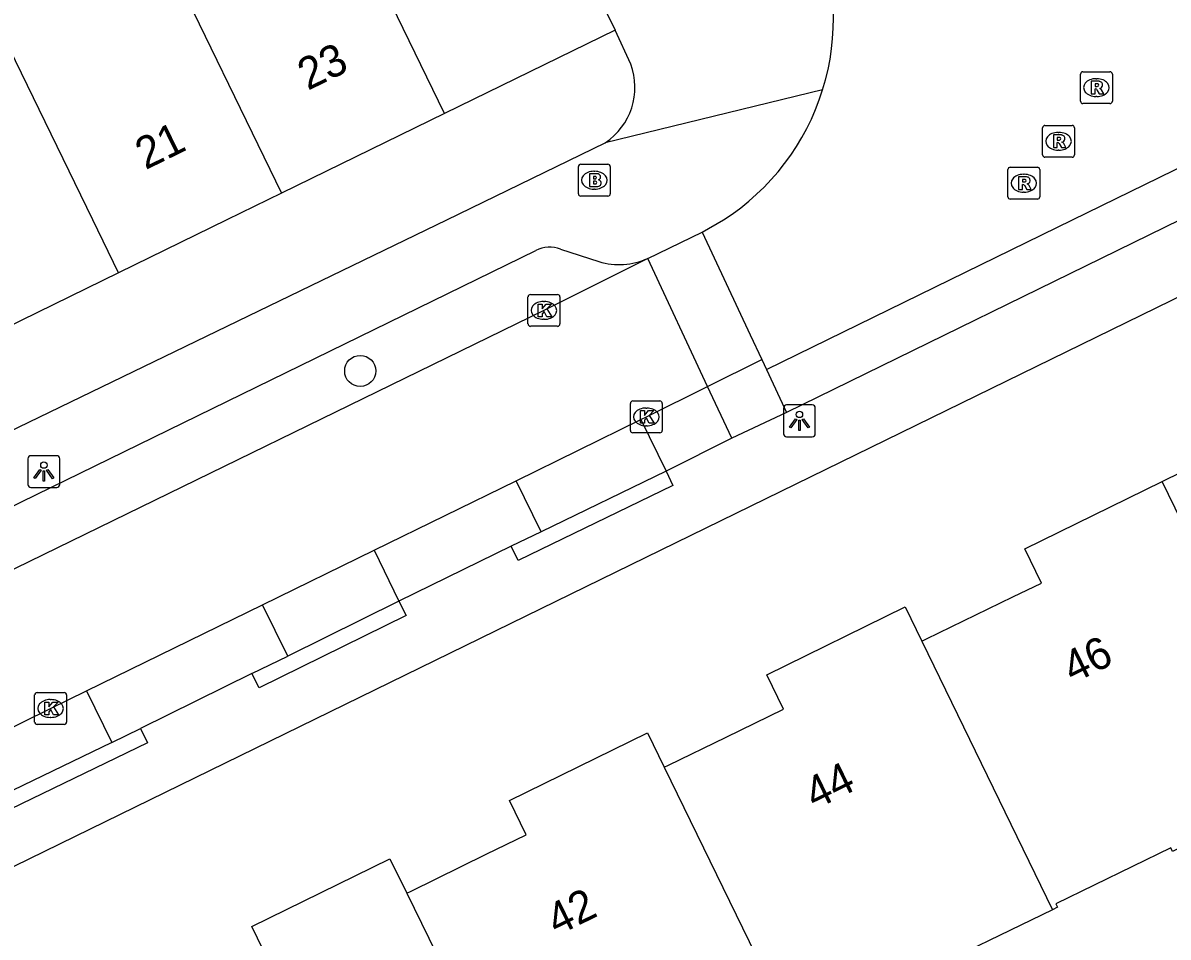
# Model space of a CAD drawing. Extents: x 160457 to 162082, y 388340 to 389736.
# Drawn here: x 160836.83 to 160872.78, y 388727.48 to 388756.19 of the extents above; entities that cross this region are included whole.
import ezdxf

# ---------------------------------------------------------------- set-up
doc = ezdxf.new("R2010")
doc.units = 0
for name, color, linetype in [('IMGEO_Boom', 7, 'Continuous'), ('IMGEO_Brandkraan', 7, 'Continuous'), ('IMGEO_Kolk', 7, 'Continuous'), ('IMGEO_Lichtpunt', 7, 'Continuous'), ('IMGEO_Pand', 7, 'Continuous'), ('IMGEO_Pand_nummerreeks', 7, 'Continuous'), ('IMGEO_Parkeervlak_open', 7, 'Continuous'), ('IMGEO_Rijbaan_lokaal_gesloten', 7, 'Continuous'), ('IMGEO_Rijbaan_lokaal_open', 7, 'Continuous'), ('IMGEO_Rioolput', 7, 'Continuous'), ('IMGEO_Voetpad_open', 7, 'Continuous')]:
    doc.layers.add(name, color=color, linetype=linetype)

msp = doc.modelspace()

# ---------------------------------------------------------------- linework, layer by layer
at = {"layer": 'IMGEO_Boom'}
msp.add_circle((160847.424, 388745.255), 0.489, dxfattribs=at)
at = {"layer": 'IMGEO_Brandkraan'}
for p, q in [((160854.347, 388751.746), (160855.199, 388751.746)), ((160854.272, 388750.82), (160854.272, 388751.672)), ((160854.76, 388751.526), (160854.785, 388751.526)), ((160855.273, 388751.672), (160855.273, 388750.82)), ((160855.199, 388750.746), (160854.347, 388750.746)), ((160854.783, 388750.966), (160854.758, 388750.966))]:
    msp.add_line(p, q, dxfattribs=at)
for points in [[(160854.347, 388751.746), (160855.199, 388751.746)], [(160854.272, 388750.82), (160854.272, 388751.672)], [(160854.62, 388751.446), (160854.62, 388751.046), (160854.833, 388751.046)], [(160854.851, 388751.446), (160854.62, 388751.446)], [(160854.799, 388751.365), (160854.745, 388751.365), (160854.745, 388751.289)], [(160855.273, 388751.672), (160855.273, 388750.82)], [(160854.745, 388751.289), (160854.798, 388751.289)], [(160854.807, 388751.213), (160854.745, 388751.213), (160854.745, 388751.132)], [(160854.745, 388751.132), (160854.807, 388751.132)], [(160855.199, 388750.746), (160854.347, 388750.746)]]:
    msp.add_lwpolyline(points, dxfattribs=at)
for centre, radius, start, end in [((160854.349, 388751.67), 0.0765, 91.552, 178.448), ((160854.349, 388751.67), 0.0765, 91.552, 178.448), ((160855.197, 388751.67), 0.0765, 1.552, 88.448), ((160855.197, 388751.67), 0.0765, 1.552, 88.448), ((160854.8, 388751.327), 0.0379, 267.8285, 90.9355), ((160854.855, 388751.301), 0.145, 59.4692, 91.5367), ((160854.88, 388751.348), 0.0922, 285.5137, 58.1501), ((160854.808, 388751.172), 0.0404, 269.8759, 90.5077), ((160854.839, 388751.297), 0.251, 268.6676, 293.5347), ((160854.885, 388751.156), 0.105, 301.3115, 78.989), ((160854.349, 388750.822), 0.0765, 181.552, 268.448), ((160854.349, 388750.822), 0.0765, 181.552, 268.448), ((160855.197, 388750.822), 0.0765, 271.552, 358.448), ((160855.197, 388750.822), 0.0765, 271.552, 358.448)]:
    msp.add_arc(centre, radius, start, end, dxfattribs=at)
for centre, major_axis, ratio, start_param, end_param in [((160854.759, 388751.246), (-0.387, 0.002), 0.722429, 4.712389, 7.853982), ((160854.784, 388751.246), (-0.39, 0.002), 0.717154, 1.570796, 4.712389)]:
    msp.add_ellipse(centre, major_axis=major_axis, ratio=ratio, start_param=start_param, end_param=end_param, dxfattribs=at)
at = {"layer": 'IMGEO_Kolk'}
for p, q in [((160852.69, 388746.731), (160852.69, 388747.583)), ((160852.765, 388747.657), (160853.617, 388747.657)), ((160853.178, 388747.437), (160853.203, 388747.437)), ((160853.691, 388747.583), (160853.691, 388746.731)), ((160853.201, 388746.877), (160853.176, 388746.877)), ((160853.617, 388746.657), (160852.765, 388746.657)), ((160855.904, 388743.386), (160855.904, 388744.238)), ((160855.979, 388744.312), (160856.831, 388744.312)), ((160856.905, 388744.238), (160856.905, 388743.386)), ((160856.392, 388744.092), (160856.417, 388744.092)), ((160856.415, 388743.532), (160856.39, 388743.532)), ((160856.831, 388743.312), (160855.979, 388743.312)), ((160837.203, 388734.229), (160837.203, 388735.081)), ((160837.278, 388735.155), (160838.13, 388735.155)), ((160837.691, 388734.935), (160837.716, 388734.935)), ((160838.204, 388735.081), (160838.204, 388734.229)), ((160838.13, 388734.155), (160837.278, 388734.155)), ((160837.714, 388734.375), (160837.689, 388734.375))]:
    msp.add_line(p, q, dxfattribs=at)
for points in [[(160852.69, 388746.731), (160852.69, 388747.583)], [(160852.765, 388747.657), (160853.617, 388747.657)], [(160853.691, 388747.583), (160853.691, 388746.731)], [(160853.011, 388747.357), (160853.134, 388747.357), (160853.134, 388747.206), (160853.264, 388747.357), (160853.428, 388747.357), (160853.282, 388747.206), (160853.435, 388746.957), (160853.283, 388746.957), (160853.198, 388747.121), (160853.134, 388747.054), (160853.134, 388746.957), (160853.011, 388746.957), (160853.011, 388747.357)], [(160853.617, 388746.657), (160852.765, 388746.657)], [(160855.904, 388743.386), (160855.904, 388744.238)], [(160855.979, 388744.312), (160856.831, 388744.312)], [(160856.905, 388744.238), (160856.905, 388743.386)], [(160856.225, 388744.012), (160856.348, 388744.012), (160856.348, 388743.861), (160856.478, 388744.012), (160856.642, 388744.012), (160856.496, 388743.861), (160856.649, 388743.612), (160856.497, 388743.612), (160856.412, 388743.776), (160856.348, 388743.709), (160856.348, 388743.612), (160856.225, 388743.612), (160856.225, 388744.012)], [(160856.831, 388743.312), (160855.979, 388743.312)], [(160837.203, 388734.229), (160837.203, 388735.081)], [(160837.278, 388735.155), (160838.13, 388735.155)], [(160837.524, 388734.855), (160837.647, 388734.855), (160837.647, 388734.704), (160837.777, 388734.855), (160837.941, 388734.855), (160837.795, 388734.704), (160837.948, 388734.455), (160837.796, 388734.455), (160837.711, 388734.619), (160837.647, 388734.552), (160837.647, 388734.455), (160837.524, 388734.455), (160837.524, 388734.855)], [(160838.204, 388735.081), (160838.204, 388734.229)], [(160838.13, 388734.155), (160837.278, 388734.155)]]:
    msp.add_lwpolyline(points, dxfattribs=at)
for centre, start, end in [((160852.767, 388747.581), 91.552, 178.448), ((160852.767, 388747.581), 91.552, 178.448), ((160853.615, 388747.581), 1.552, 88.448), ((160853.615, 388747.581), 1.552, 88.448), ((160852.767, 388746.733), 181.552, 268.448), ((160852.767, 388746.733), 181.552, 268.448), ((160853.615, 388746.733), 271.552, 358.448), ((160853.615, 388746.733), 271.552, 358.448), ((160855.981, 388744.236), 91.552, 178.448), ((160855.981, 388744.236), 91.552, 178.448), ((160856.829, 388744.236), 1.552, 88.448), ((160856.829, 388744.236), 1.552, 88.448), ((160855.981, 388743.388), 181.552, 268.448), ((160855.981, 388743.388), 181.552, 268.448), ((160856.829, 388743.388), 271.552, 358.448), ((160856.829, 388743.388), 271.552, 358.448), ((160837.28, 388735.079), 91.552, 178.448), ((160837.28, 388735.079), 91.552, 178.448), ((160838.128, 388735.079), 1.552, 88.448), ((160838.128, 388735.079), 1.552, 88.448), ((160837.28, 388734.231), 181.552, 268.448), ((160837.28, 388734.231), 181.552, 268.448), ((160838.128, 388734.231), 271.552, 358.448), ((160838.128, 388734.231), 271.552, 358.448)]:
    msp.add_arc(centre, 0.0765, start, end, dxfattribs=at)
for centre, major_axis, ratio, start_param, end_param in [((160853.177, 388747.157), (-0.387, 0.002), 0.722429, 4.712389, 7.853982), ((160853.202, 388747.157), (-0.39, 0.002), 0.717154, 1.570796, 4.712389), ((160856.391, 388743.812), (-0.387, 0.002), 0.722429, 4.712389, 7.853982), ((160856.416, 388743.812), (-0.39, 0.002), 0.717154, 1.570796, 4.712389), ((160837.69, 388734.655), (-0.387, 0.002), 0.722429, 4.712389, 7.853982), ((160837.715, 388734.655), (-0.39, 0.002), 0.717154, 1.570796, 4.712389)]:
    msp.add_ellipse(centre, major_axis=major_axis, ratio=ratio, start_param=start_param, end_param=end_param, dxfattribs=at)
at = {"layer": 'IMGEO_Lichtpunt'}
for p, q in [((160861.615, 388744.187), (160860.807, 388744.187)), ((160861.615, 388744.187), (160860.807, 388744.187)), ((160860.713, 388744.092), (160860.713, 388743.285)), ((160860.713, 388744.092), (160860.713, 388743.285)), ((160861.709, 388743.285), (160861.709, 388744.092)), ((160861.709, 388743.285), (160861.709, 388744.092)), ((160860.807, 388743.191), (160861.615, 388743.191)), ((160860.807, 388743.191), (160861.615, 388743.191)), ((160836.992, 388742.499), (160836.992, 388741.692)), ((160836.992, 388742.499), (160836.992, 388741.692)), ((160837.894, 388742.594), (160837.086, 388742.594)), ((160837.894, 388742.594), (160837.086, 388742.594)), ((160837.988, 388741.692), (160837.988, 388742.499)), ((160837.988, 388741.692), (160837.988, 388742.499)), ((160837.086, 388741.598), (160837.894, 388741.598)), ((160837.086, 388741.598), (160837.894, 388741.598))]:
    msp.add_line(p, q, dxfattribs=at)
for points in [[(160861.087, 388743.756), (160861.126, 388743.728), (160860.938, 388743.466), (160860.9, 388743.493), (160861.087, 388743.756)], [(160861.189, 388743.708), (160861.236, 388743.708), (160861.236, 388743.386), (160861.189, 388743.386), (160861.189, 388743.708)], [(160861.299, 388743.728), (160861.337, 388743.755), (160861.524, 388743.493), (160861.485, 388743.465), (160861.299, 388743.728)], [(160837.366, 388742.163), (160837.405, 388742.135), (160837.217, 388741.873), (160837.179, 388741.9), (160837.366, 388742.163)], [(160837.468, 388742.115), (160837.515, 388742.115), (160837.515, 388741.793), (160837.468, 388741.793), (160837.468, 388742.115)], [(160837.578, 388742.135), (160837.616, 388742.162), (160837.803, 388741.9), (160837.764, 388741.872), (160837.578, 388742.135)]]:
    msp.add_lwpolyline(points, dxfattribs=at)
for centre in [(160861.212, 388743.89), (160837.491, 388742.297)]:
    msp.add_circle(centre, 0.0994, dxfattribs=at)
for centre, start, end in [((160860.807, 388744.092), 90, 180), ((160860.807, 388744.092), 90, 180), ((160861.615, 388744.092), 0, 90), ((160861.615, 388744.092), 0, 90), ((160860.807, 388743.285), 180, 270), ((160860.807, 388743.285), 180, 270), ((160861.615, 388743.285), 270, 0), ((160861.615, 388743.285), 270, 360), ((160837.086, 388742.499), 90, 180), ((160837.086, 388742.499), 90, 180), ((160837.894, 388742.499), 0, 90), ((160837.894, 388742.499), 0, 90), ((160837.086, 388741.692), 180, 270), ((160837.086, 388741.692), 180, 270), ((160837.894, 388741.692), 270, 0), ((160837.894, 388741.692), 270, 360)]:
    msp.add_arc(centre, 0.0946, start, end, dxfattribs=at)
at = {"layer": 'IMGEO_Pand'}
for points in [[(160850.954, 388765.091), (160855.423, 388755.962)], [(160850.072, 388753.345), (160846.377, 388760.947)], [(160841.258, 388758.447), (160844.955, 388750.843)], [(160839.837, 388748.341), (160839.03, 388750), (160835.476, 388757.311)], [(160855.423, 388755.962), (160850.072, 388753.345)], [(160850.072, 388753.345), (160844.955, 388750.843)], [(160844.955, 388750.843), (160843.231, 388750), (160839.837, 388748.341)], [(160839.837, 388748.341), (160834.719, 388745.838)], [(160872.599, 388741.787), (160876.898, 388743.896), (160877.427, 388742.819), (160879.228, 388743.7), (160881.029, 388744.581), (160881.194, 388744.662)], [(160865.055, 388736.772), (160865.201, 388736.843), (160867.913, 388738.157), (160868.811, 388738.592), (160868.282, 388739.669), (160872.599, 388741.787)], [(160877.233, 388732.263), (160872.599, 388741.787)], [(160856.967, 388732.811), (160857.102, 388732.877), (160858.907, 388733.756), (160860.713, 388734.636), (160860.184, 388735.713), (160864.533, 388737.845), (160865.055, 388736.772)], [(160865.055, 388736.772), (160869.159, 388728.337)], [(160848.884, 388728.851), (160849.024, 388728.92), (160851.382, 388730.075), (160852.633, 388730.688), (160852.105, 388731.765), (160856.441, 388733.89), (160856.967, 388732.811)], [(160856.967, 388732.811), (160861.066, 388724.401)], [(160877.233, 388732.263), (160872.919, 388730.166), (160872.867, 388730.274), (160869.261, 388728.52), (160869.313, 388728.412), (160869.159, 388728.337)], [(160840.791, 388724.896), (160840.938, 388724.968), (160842.199, 388725.586), (160843.1, 388726.028), (160844.542, 388726.734), (160844.016, 388727.813), (160848.357, 388729.929), (160848.884, 388728.851)], [(160848.884, 388728.851), (160853.04, 388720.353)], [(160869.159, 388728.337), (160864.835, 388726.234), (160864.782, 388726.342), (160861.167, 388724.584), (160861.22, 388724.476), (160861.066, 388724.401)]]:
    msp.add_lwpolyline(points, dxfattribs=at)
at = {"layer": 'IMGEO_Parkeervlak_open'}
for points in [[(160860.175, 388745.303), (160860.806, 388743.953)], [(160859.088, 388743.145), (160858.322, 388744.767)], [(160856.229, 388743.727), (160857.023, 388742.106)], [(160853.099, 388740.207), (160852.314, 388741.81)], [(160847.856, 388739.627), (160848.64, 388738.026)], [(160845.146, 388736.302), (160844.357, 388737.914)], [(160838.835, 388735.21), (160839.629, 388733.589)]]:
    msp.add_lwpolyline(points, dxfattribs=at)
at = {"layer": 'IMGEO_Rijbaan_lokaal_gesloten'}
for points in [[(160856.45, 388748.792), (160853.191, 388747.155), (160836.158, 388738.845), (160817.647, 388729.787), (160814.348, 388728.165)], [(160856.229, 388743.727), (160856.405, 388743.813), (160858.322, 388744.767)], [(160852.314, 388741.81), (160856.229, 388743.727)], [(160847.856, 388739.627), (160852.314, 388741.81)], [(160844.357, 388737.914), (160847.856, 388739.627)], [(160838.835, 388735.21), (160844.357, 388737.914)], [(160835.109, 388733.382), (160837.704, 388734.656), (160838.835, 388735.21)]]:
    msp.add_lwpolyline(points, dxfattribs=at)
at = {"layer": 'IMGEO_Rijbaan_lokaal_open'}
for points in [[(160860.175, 388745.303), (160869.779, 388750), (160878.433, 388754.232)], [(160858.158, 388749.617), (160858.828, 388750)], [(160856.45, 388748.792), (160858.158, 388749.617)], [(160858.158, 388749.617), (160859.667, 388746.388), (160860.028, 388745.616)], [(160858.322, 388744.767), (160856.45, 388748.792)], [(160858.322, 388744.767), (160860.028, 388745.616)], [(160860.028, 388745.616), (160860.175, 388745.303)]]:
    msp.add_lwpolyline(points, dxfattribs=at)
for centre, radius, start, end in [((160854.771, 388756.32), 7.509, 342.6866, 22.6715), ((160854.772, 388756.318), 7.508, 302.701, 342.6979)]:
    msp.add_arc(centre, radius, start, end, dxfattribs=at)
at = {"layer": 'IMGEO_Rioolput'}
for p, q in [((160870.033, 388753.728), (160870.033, 388754.58)), ((160870.108, 388754.654), (160870.96, 388754.654)), ((160871.034, 388754.58), (160871.034, 388753.728)), ((160870.521, 388754.434), (160870.546, 388754.434)), ((160870.544, 388753.874), (160870.519, 388753.874)), ((160870.96, 388753.654), (160870.108, 388753.654)), ((160868.845, 388752.042), (160868.845, 388752.894)), ((160868.92, 388752.968), (160869.772, 388752.968)), ((160869.846, 388752.894), (160869.846, 388752.042)), ((160869.333, 388752.748), (160869.358, 388752.748)), ((160869.356, 388752.188), (160869.331, 388752.188)), ((160869.772, 388751.968), (160868.92, 388751.968)), ((160867.755, 388750.726), (160867.755, 388751.578)), ((160867.83, 388751.652), (160868.682, 388751.652)), ((160868.243, 388751.432), (160868.268, 388751.432)), ((160868.756, 388751.578), (160868.756, 388750.726)), ((160868.682, 388750.652), (160867.83, 388750.652)), ((160868.266, 388750.872), (160868.241, 388750.872))]:
    msp.add_line(p, q, dxfattribs=at)
for points in [[(160870.033, 388753.728), (160870.033, 388754.58)], [(160870.108, 388754.654), (160870.96, 388754.654)], [(160871.034, 388754.58), (160871.034, 388753.728)], [(160870.622, 388754.352), (160870.37, 388754.354), (160870.37, 388753.954)], [(160870.548, 388754.273), (160870.494, 388754.273), (160870.494, 388754.192)], [(160870.37, 388753.954), (160870.494, 388753.954), (160870.494, 388754.116), (160870.505, 388754.116)], [(160870.494, 388754.192), (160870.546, 388754.192)], [(160870.552, 388754.087), (160870.623, 388753.954), (160870.763, 388753.954), (160870.698, 388754.08)], [(160870.96, 388753.654), (160870.108, 388753.654)], [(160868.845, 388752.042), (160868.845, 388752.894)], [(160868.92, 388752.968), (160869.772, 388752.968)], [(160869.846, 388752.894), (160869.846, 388752.042)], [(160869.434, 388752.666), (160869.182, 388752.668), (160869.182, 388752.268)], [(160869.182, 388752.268), (160869.306, 388752.268), (160869.306, 388752.43), (160869.317, 388752.43)], [(160869.36, 388752.587), (160869.306, 388752.587), (160869.306, 388752.506)], [(160869.306, 388752.506), (160869.358, 388752.506)], [(160869.364, 388752.401), (160869.435, 388752.268), (160869.575, 388752.268), (160869.51, 388752.394)], [(160869.772, 388751.968), (160868.92, 388751.968)], [(160867.755, 388750.726), (160867.755, 388751.578)], [(160867.83, 388751.652), (160868.682, 388751.652)], [(160868.344, 388751.35), (160868.092, 388751.352), (160868.092, 388750.952)], [(160868.756, 388751.578), (160868.756, 388750.726)], [(160868.092, 388750.952), (160868.216, 388750.952), (160868.216, 388751.114), (160868.227, 388751.114)], [(160868.27, 388751.271), (160868.216, 388751.271), (160868.216, 388751.19)], [(160868.216, 388751.19), (160868.268, 388751.19)], [(160868.274, 388751.085), (160868.345, 388750.952), (160868.485, 388750.952), (160868.42, 388751.078)], [(160868.682, 388750.652), (160867.83, 388750.652)]]:
    msp.add_lwpolyline(points, dxfattribs=at)
for centre, radius, start, end in [((160870.11, 388754.578), 0.0765, 91.552, 178.448), ((160870.11, 388754.578), 0.0765, 91.552, 178.448), ((160870.958, 388754.578), 0.0765, 1.552, 88.448), ((160870.958, 388754.578), 0.0765, 1.552, 88.448), ((160870.554, 388754.177), 0.0964, 77.0061, 93.1865), ((160870.568, 388754.234), 0.0378, 276.6634, 79.6772), ((160870.621, 388754.242), 0.109, 350.3612, 89.416), ((160870.619, 388754.242), 0.112, 277.5842, 350.9817), ((160870.504, 388754.063), 0.0533, 26.0293, 88.6989), ((160870.53, 388754.381), 0.19, 274.7715, 282.9687), ((160870.603, 388754.027), 0.108, 29.5134, 73.7905), ((160870.11, 388753.73), 0.0765, 181.552, 268.448), ((160870.11, 388753.73), 0.0765, 181.552, 268.448), ((160870.958, 388753.73), 0.0765, 271.552, 358.448), ((160870.958, 388753.73), 0.0765, 271.552, 358.448), ((160868.922, 388752.892), 0.0765, 91.552, 178.448), ((160868.922, 388752.892), 0.0765, 91.552, 178.448), ((160869.77, 388752.892), 0.0765, 1.552, 88.448), ((160869.77, 388752.892), 0.0765, 1.552, 88.448), ((160869.316, 388752.377), 0.0533, 26.0293, 88.6989), ((160869.342, 388752.695), 0.19, 274.7715, 282.9687), ((160869.366, 388752.491), 0.0964, 77.0061, 93.1865), ((160869.38, 388752.548), 0.0378, 276.6634, 79.6772), ((160869.433, 388752.556), 0.109, 350.3612, 89.416), ((160869.431, 388752.556), 0.112, 277.5842, 350.9817), ((160869.415, 388752.341), 0.108, 29.5134, 73.7905), ((160868.922, 388752.044), 0.0765, 181.552, 268.448), ((160868.922, 388752.044), 0.0765, 181.552, 268.448), ((160869.77, 388752.044), 0.0765, 271.552, 358.448), ((160869.77, 388752.044), 0.0765, 271.552, 358.448), ((160867.832, 388751.576), 0.0765, 91.552, 178.448), ((160867.832, 388751.576), 0.0765, 91.552, 178.448), ((160868.343, 388751.24), 0.109, 350.3612, 89.416), ((160868.68, 388751.576), 0.0765, 1.552, 88.448), ((160868.68, 388751.576), 0.0765, 1.552, 88.448), ((160868.226, 388751.061), 0.0533, 26.0293, 88.6989), ((160868.252, 388751.379), 0.19, 274.7715, 282.9687), ((160868.276, 388751.175), 0.0964, 77.0061, 93.1865), ((160868.29, 388751.232), 0.0378, 276.6634, 79.6772), ((160868.341, 388751.24), 0.112, 277.5842, 350.9817), ((160868.325, 388751.025), 0.108, 29.5134, 73.7905), ((160867.832, 388750.728), 0.0765, 181.552, 268.448), ((160867.832, 388750.728), 0.0765, 181.552, 268.448), ((160868.68, 388750.728), 0.0765, 271.552, 358.448), ((160868.68, 388750.728), 0.0765, 271.552, 358.448)]:
    msp.add_arc(centre, radius, start, end, dxfattribs=at)
for centre, major_axis, ratio, start_param, end_param in [((160870.52, 388754.154), (-0.387, 0.002), 0.722429, 4.712389, 7.853982), ((160870.545, 388754.154), (-0.39, 0.002), 0.717154, 1.570796, 4.712389), ((160869.332, 388752.468), (-0.387, 0.002), 0.722429, 4.712389, 7.853982), ((160869.357, 388752.468), (-0.39, 0.002), 0.717154, 1.570796, 4.712389), ((160868.242, 388751.152), (-0.387, 0.002), 0.722429, 4.712389, 7.853982), ((160868.267, 388751.152), (-0.39, 0.002), 0.717154, 1.570796, 4.712389)]:
    msp.add_ellipse(centre, major_axis=major_axis, ratio=ratio, start_param=start_param, end_param=end_param, dxfattribs=at)
at = {"layer": 'IMGEO_Voetpad_open'}
for points in [[(160929.117, 388774.962), (160878.066, 388750), (160811.085, 388717.249)], [(160855.915, 388754.895), (160855.423, 388755.962)], [(160861.94, 388754.085), (160855.113, 388752.423)], [(160879.107, 388752.907), (160873.165, 388750), (160860.806, 388743.953)], [(160824.212, 388737.448), (160850.145, 388750), (160855.113, 388752.423)], [(160816.007, 388730.993), (160852.935, 388749.039)], [(160853.711, 388749.081), (160854.918, 388748.69)], [(160860.806, 388743.953), (160859.088, 388743.145)], [(160859.088, 388743.145), (160857.023, 388742.106)], [(160857.023, 388742.106), (160857.24, 388741.656), (160852.379, 388739.303), (160852.162, 388739.753)], [(160857.023, 388742.106), (160853.099, 388740.207)], [(160853.099, 388740.207), (160852.162, 388739.753)], [(160852.162, 388739.753), (160848.64, 388738.026)], [(160848.64, 388738.026), (160848.861, 388737.578), (160844.246, 388735.301), (160844.025, 388735.749)], [(160848.64, 388738.026), (160845.146, 388736.302)], [(160844.025, 388735.749), (160845.146, 388736.302)], [(160844.025, 388735.749), (160840.529, 388734.025)], [(160840.529, 388734.025), (160840.746, 388733.575), (160836.112, 388731.332), (160835.895, 388731.782)], [(160839.629, 388733.589), (160840.529, 388734.025)], [(160839.629, 388733.589), (160835.895, 388731.782)]]:
    msp.add_lwpolyline(points, dxfattribs=at)
for centre, radius, start, end in [((160853.966, 388754.161), 2.083, 303.4237, 20.6267), ((160853.37, 388748.194), 0.95, 68.9563, 117.2397), ((160855.549, 388750.767), 2.171, 253.0972, 294.521)]:
    msp.add_arc(centre, radius, start, end, dxfattribs=at)

# ---------------------------------------------------------------- texts
at = {"layer": 'IMGEO_Pand_nummerreeks'}
for s, rotation, p in [('23', 26.0581, (160845.779, 388754.051)), ('21', 26.0581, (160840.683, 388751.56)), ('46', 26.0696, (160869.791, 388735.427)), ('44', 26.0696, (160861.693, 388731.466)), ('42', 26.0696, (160853.592, 388727.503))]:
    msp.add_text(s, height=1, rotation=rotation, dxfattribs=at).set_placement(p)

doc.saveas('drawing.dxf')
